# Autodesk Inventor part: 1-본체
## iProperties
Created: 2015-06
Part Number: 1-본체
Document SubType Name: Modeling
Designer: Administrator
Density: 2.71 g/cm^3
Material: 알루미늄-6061
Mass: 3339.68 g
Surface Area: 2298.01 cm^2
Volume: 1232.36 cm^3
Author: Administrator
